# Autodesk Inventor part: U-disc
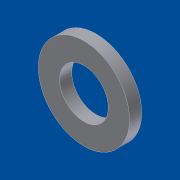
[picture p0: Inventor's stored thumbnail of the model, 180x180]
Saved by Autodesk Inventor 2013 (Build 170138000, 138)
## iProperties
Shininess: 25.0
Length Units: 11269
Angle Units: 11279
Time Units: 11290
Mass Units: 11283
Length Display Precision: 3
Angle Display Precision: 2
Created: 2001-04
Part Number: U-disc
Material: Standard
Document SubType Name: Modellieren
Designer: dl
Density: 1 g/cm^3
Density: 0.0
Volumn: 0.0
Area: 0.0
PropertySet Name: Model Information
Control State: 0
Master: False
Checked Out: False
Author: dl
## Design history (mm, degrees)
body "Solid1"
sketch "Sketch1"
  geometry: C1 r 6 at (0, 0); C2 r 3.2 at (0, 0)
  constraints: 2 centre point, 1 coincident
  dimensions: "d0" = 6.4 diameter of C2; "d1" = 12 diameter of C1
extrude "Extrusion1" new body sketch "Sketch1" distance "d2" = 1.6; taper "d3" = 0 deg
